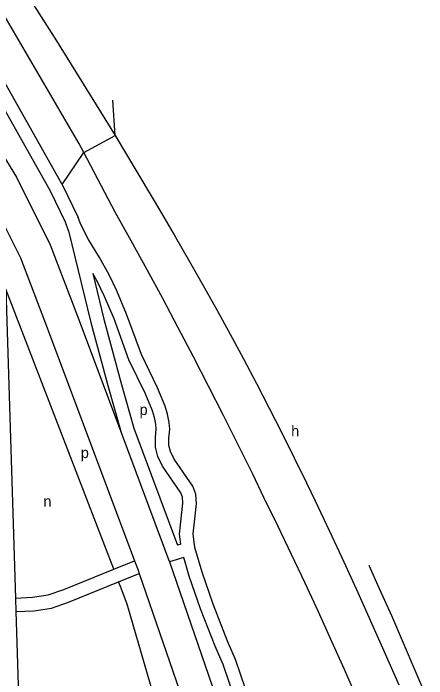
# Model space of a CAD drawing. Extents: x 159441 to 162086, y 388175 to 389787.
# Drawn here: x 161838 to 161991.3, y 388797.6 to 389044.4 of the extents above; entities that cross this region are included whole.
import ezdxf

# ---------------------------------------------------------------- set-up
doc = ezdxf.new("R2010")
doc.units = 0
for name, color, linetype in [('BLT_Basislijn', 7, 'Continuous'), ('BLT_Centroide', 7, 'Continuous'), ('BLT_Vlakafsluiter', 7, 'Continuous')]:
    doc.layers.add(name, color=color, linetype=linetype)

msp = doc.modelspace()

# ---------------------------------------------------------------- linework, layer by layer
at = {"layer": 'BLT_Basislijn'}
for p, q in [((161856.11, 388980.82), (161819.53, 389045.68)), ((161856.11, 388980.82), (161862.01, 388968.65)), ((161857.33, 388966.91), (161851.76, 388978.37)), ((161875.26, 388838.2), (161835.22, 388942.08)), ((161835.22, 388942.08), (161838.76, 388827.45)), ((161900.14, 388847.45), (161898.92, 388847.07)), ((161901.19, 388842.54), (161895.87, 388840.88)), ((161877.73, 388831.79), (161877.06, 388833.53)), ((161880.26, 388825.22), (161877.73, 388831.79)), ((161838.76, 388827.45), (161838.91, 388822.46)), ((161904.46, 388741.36), (161880.26, 388825.22))]:
    msp.add_line(p, q, dxfattribs=at)
for points in [[(161864.11, 388992.72), (161862.26, 388996.22), (161834.62, 389043.66), (161820.58, 389066.73), (161794.96, 389108.1), (161778.03, 389134.85), (161748.78, 389180.87), (161736.01, 389200.14), (161730.36, 389208.82), (161706.15, 389245.56), (161679.72, 389284.71), (161666.51, 389304.75), (161627.77, 389361.67), (161610.82, 389386.7), (161592.22, 389413.57), (161575.68, 389437.79), (161555.14, 389463.04), (161543.69, 389478.37)], [(161773.47, 389161.45), (161791.55, 389132.42), (161804.04, 389113.15), (161818.97, 389089.94), (161836.12, 389062.29), (161853.99, 389034.17), (161875.78, 388999.05)], [(161744.88, 389115.29), (161762.34, 389096.56), (161775.86, 389079.23), (161808.02, 389034.23), (161839.18, 388983.59)], [(161851.76, 388978.37), (161815.29, 389043.02)], [(161875.78, 388999.05), (161892.93, 388970.19), (161898.17, 388961.3), (161903.34, 388952.36), (161908.44, 388943.39), (161913.48, 388934.38), (161918.44, 388925.33), (161923.33, 388916.25), (161928.15, 388907.12), (161932.9, 388897.96), (161937.58, 388888.76), (161942.19, 388879.53), (161946.73, 388870.26), (161949.94, 388863.58), (161955.29, 388852.28), (161960.57, 388840.96), (161965.77, 388829.6), (161970.9, 388818.2), (161975.96, 388806.78), (161980.95, 388795.32)], [(161965.58, 388790.21), (161960.86, 388800.96), (161956.06, 388811.68), (161951.19, 388822.37), (161946.24, 388833.03), (161941.23, 388843.65), (161936.14, 388854.24), (161930.98, 388864.79), (161926.8, 388873.41), (161921.42, 388884.35), (161915.96, 388895.26), (161910.43, 388906.13), (161904.83, 388916.97), (161899.17, 388927.77), (161893.42, 388938.53), (161887.61, 388949.26), (161881.73, 388959.94), (161875.78, 388970.59), (161864.11, 388992.72)], [(161839.18, 388983.59), (161851.63, 388958.47), (161861.8, 388932.02), (161877.94, 388888.89)], [(161931.5, 388772.11), (161920.45, 388804.67), (161917.48, 388811.54), (161912.08, 388825.22), (161907.98, 388837.09), (161905.34, 388846.19), (161904.68, 388851.28), (161905.9, 388862.5), (161905.73, 388866.03), (161904.54, 388868.96), (161897.71, 388878.97), (161896.32, 388881.8), (161895.7, 388884.09), (161895.68, 388886.82), (161895.99, 388890.18), (161895.85, 388892.64), (161895.23, 388895.7), (161894.26, 388898.64), (161891.44, 388905.5), (161885.5, 388917.81), (161880, 388932.83), (161876.39, 388941.47), (161873.48, 388947.32), (161869.92, 388953.82), (161865.87, 388960.5), (161862.98, 388966.05), (161862.01, 388968.65)], [(161834.47, 388966.07), (161840.63, 388953.64), (161850.58, 388927.76), (161882.93, 388841.3)], [(161858.51, 388963.73), (161857.33, 388966.91)], [(161858.51, 388963.73), (161866.71, 388929.7), (161873.07, 388906.28), (161877.94, 388888.89)], [(161867.47, 388947.88), (161871.55, 388930.94), (161877.89, 388907.61), (161882.7, 388890.44)], [(161900.14, 388847.45), (161899.65, 388851.23), (161900.88, 388862.65), (161900.78, 388864.94), (161900.11, 388866.58), (161893.37, 388876.45), (161891.62, 388880.03), (161890.71, 388883.4), (161890.68, 388887.03), (161890.98, 388890.26), (161890.88, 388891.99), (161890.38, 388894.42), (161889.57, 388896.91), (161886.88, 388903.46), (161880.89, 388915.86), (161875.34, 388931), (161871.84, 388939.39), (161869.05, 388945.01), (161867.47, 388947.88)], [(161882.7, 388890.44), (161898.92, 388847.07)], [(161877.94, 388888.89), (161895.54, 388841.85), (161895.87, 388840.88)], [(161926.8, 388770.41), (161915.79, 388802.87), (161912.86, 388809.63), (161907.39, 388823.49), (161903.21, 388835.58), (161901.19, 388842.54)], [(161875.26, 388838.2), (161882.93, 388841.3)], [(161882.93, 388841.3), (161884.24, 388837.79), (161884.65, 388836.6)], [(161895.87, 388840.88), (161922.34, 388764.08), (161947.99, 388685.46), (161966.14, 388627.2), (161970.07, 388609.03)], [(161838.76, 388827.45), (161845.06, 388827.79), (161850.87, 388828.64), (161856.67, 388830.7), (161875.26, 388838.2)], [(161991.34, 388790.51), (161987.09, 388800.67), (161982.76, 388810.8), (161978.36, 388820.89), (161973.89, 388830.96), (161969.96, 388839.63)], [(161877.06, 388833.53), (161884.65, 388836.6)], [(161884.65, 388836.6), (161910.96, 388760.26), (161936.55, 388681.81), (161954.58, 388623.98), (161958.28, 388608.97), (161959.77, 388601.99)], [(161838.91, 388822.46), (161845.56, 388822.81), (161852.08, 388823.77), (161858.44, 388826.03), (161877.06, 388833.53)], [(161838.91, 388822.46), (161839.27, 388810.87)], [(161839.27, 388810.87), (161841.45, 388740.16)]]:
    msp.add_lwpolyline(points, dxfattribs=at)
at = {"layer": 'BLT_Vlakafsluiter'}
for p, q in [((161864.11, 388992.72), (161875.78, 388999.05)), ((161856.11, 388980.82), (161864.11, 388992.72))]:
    msp.add_line(p, q, dxfattribs=at)
msp.add_lwpolyline([(161875.78, 388999.05), (161874.88, 389012.18)], dxfattribs=at)

# ---------------------------------------------------------------- texts
at = {"layer": 'BLT_Centroide'}
for s, p in [('p', (161884.81, 388895.37)), ('h', (161941.06, 388887.47)), ('p', (161863.03, 388879.42)), ('n', (161849.15, 388861.38))]:
    msp.add_text(s, height=4, dxfattribs=at).set_placement(p)

doc.saveas('drawing.dxf')
